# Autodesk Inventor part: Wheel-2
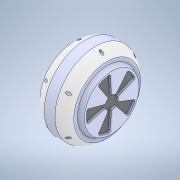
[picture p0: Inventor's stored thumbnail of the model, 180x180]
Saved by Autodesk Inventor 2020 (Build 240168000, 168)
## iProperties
Created: 2020-04
Part Number: Wheel-2
Material: Générique
Document SubType Name: Modeling
Designer: bruno
Density: 1 g/cm^3
Appearance: Par défaut
Mass: 1294.26 g
Surface Area: 715.733 cm^2
Volume: 1294.26 cm^3
Sending System: SolidWorks 2017
Last Author: hpras
Last Saved: 2020-04-23
Author: bruno
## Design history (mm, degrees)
feature "CirPattern2"
sketch "Esquisse1"
  geometry: C1 r 12.7 at (0, 0); A1 r 12.7 centre (0, 0) between (6.917, -10.651) and (11.413, -5.57) reference; A2 r 12.7 centre (0, 0) between (-7.992, -9.87) and (0.665, -12.683) reference; A3 r 12.7 centre (0, 0) between (-11.856, 4.551) and (-11.856, -4.551) reference; A4 r 12.7 centre (0, 0) between (0.665, 12.683) and (-7.992, 9.87) reference; A5 r 12.7 centre (0, 0) between (11.413, 5.57) and (6.917, 10.651) reference; 11 further points
  constraints: 1 centre point, 1 coincident, 1 concentric
extrude "Extrusion1" join sketch "Esquisse1" distance "d0" = 10; taper "d1" = 0 deg
chamfer "Chanfrein1" distance "d2" = 0.5; stored, may be unused: second distance "d3" = 2, angle "d4" = 45 deg
sketch "Esquisse2"
  geometry: L1 (15.777, 80)-(-33.547, 80); L2 (-33.547, 80)-(-33.547, 89.418); L3 (-33.547, 89.418)-(15.777, 89.418); L4 (15.777, 89.418)-(15.777, 80); L5 (0, 0)-(49.987, 0)
  constraints: 10 end point, 2 horizontal, 2 parallel, 1 perpendicular
  dimensions: "d5" = 80 distance from line of L1 L5.start
revolve "Révolution1" sketch "Esquisse2" stored, may be unused: angle "d6" = 90 deg
sketch "Esquisse3"
  geometry: L1 (0, 0)-(0, 75); C1 r 2.5 at (0, 75)
  constraints: 2 end point, 1 centre point, 1 coincident, 1 vertical
  dimensions: "d7" = 75 distance of L1.start L1.end; "d8" = 5 diameter of C1
extrude "Extrusion2" cut sketch "Esquisse3" distance "d9" = 100; taper "d10" = 0 deg
pattern_circular "Réseau circulaire1" dims angle "d12" = 360 deg
node "Solide1"
